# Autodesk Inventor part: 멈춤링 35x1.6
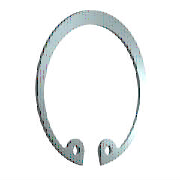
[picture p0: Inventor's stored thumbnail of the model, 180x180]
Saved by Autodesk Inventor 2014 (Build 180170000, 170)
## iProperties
IsCustomPart: 1
Created: 2015-09
Part Number: 멈춤링 35x1.6
Material: 강철, 연강
Description: 리테이닝 링(C형)
Document SubType Name: Modeling
Standard: KS B 1336
Designer: mduedu
Standards Organization: KS
Language: ko-KR
Size Designation: 35x1.6
Categories: <MemberInstance><Categories><Category DisplayName="샤프트 부품" InternalName="7f7aeb1f-a693-4053-b835-cee3144e0d98" Mnemonic="SHFT"><Category DisplayName="써클립" Inter
Density: 7.86 g/cm^3
Mass: 3.5371 g
Surface Area: 9.09651 cm^2
Volume: 0.450013 cm^3
Appearance: Blue - Wall Paint - Glossy
Author: mduedu
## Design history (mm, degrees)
sketch "스케치1"
  geometry: L1 (0, 15.113)-(0, -73.177) reference; L2 (-45.5, 0)-(45.5, 0) reference; L3 (-4.964, 1)-(1.502, 1); L4 (0, -2.5)-(-5.307, -2.5); L5 (0, -17.5)-(-8.583, -33.888); L6 (-8.583, -33.888)-(-21.772, -26.981); L7 (-7.377, -31.585)-(-17.631, -26.214); L8 (-5.162, -32.745)-(-6.29, -34.898); L9 (5.162, -32.745)-(6.29, -34.898); C1 r 1.25 at (-7.377, -31.585); C2 r 1.25 at (7.377, -31.585); A1 r 15.875 centre (0, -18.375) between (11.82, -28.972) and (-11.82, -28.972); A2 r 18.5 centre (0, -17.5) between (6.29, -34.898) and (-6.29, -34.898); A3 r 2.5 centre (-7.377, -31.585) between (-5.162, -32.745) and (-8.668, -29.444); A4 r 2.5 centre (-9.959, -27.303) between (-11.82, -28.972) and (-8.668, -29.444); A5 r 2.5 centre (9.959, -27.303) between (8.668, -29.444) and (11.82, -28.972); A6 r 2.5 centre (7.377, -31.585) between (8.668, -29.444) and (5.162, -32.745); 3 further points
  constraints: 15 point on circle, 14 end point, 9 symmetric about line, 8 centre point, 6 tangent, 4 coincident, 4 point on line, 3 perpendicular, 1 parallel, 4 other
  dimensions: "d8" = 0.875 distance of A1.centre L5.start (= 0.25 x SRB1); "d38" = 3.5 distance between parallel lines of L4 L3 (= SRB1); "d39" = 17.5 distance from line of L5.start L2 (= 0.5 x WD); "d43" = 18.5 radius of A2 (= 0.5 x ND); "d45" = 2.6 distance between parallel lines of L7 L6 (= 0.5 x SRB2); "d46" = 2.5 radius of A4 (= SD5); "d47" = 6.29 distance from line of L1 L8.end (= 0.17 x ND); "d48" = 2.5 diameter of C1 (= SD5); "d49" = 2.5 radius of A3 (= SD5)
extrude "본체" new body sketch "스케치1" distance "d2" = 1.6 (= SD); taper "d3" = 0 deg
workaxis "Work Axis1"
workaxis "Work Axis2"
workplane "Work Plane1"
body "Solid1"
other parameters: "WD" = 35 [user parameter; used in 3 equation terms], "SD" = 1.6 [user parameter; used in 1 equation term], "SRB1" = 3.5 [user parameter; used in 2 equation terms], "ND" = 37 [user parameter; used in 2 equation terms], "SRB2" = 5.2 [user parameter; used in 1 equation term], "SD5" = 2.5 [user parameter; used in 3 equation terms], "d50" = 0, "d51" = 0, "d52" = 0, "d53" = 0, "WDMIN" = 34 [user parameter], "SD6" = 37.8 [user parameter], "WDMAX" = 35 (= WD) [user parameter], "NND" = 35 (= WD) [user parameter]
